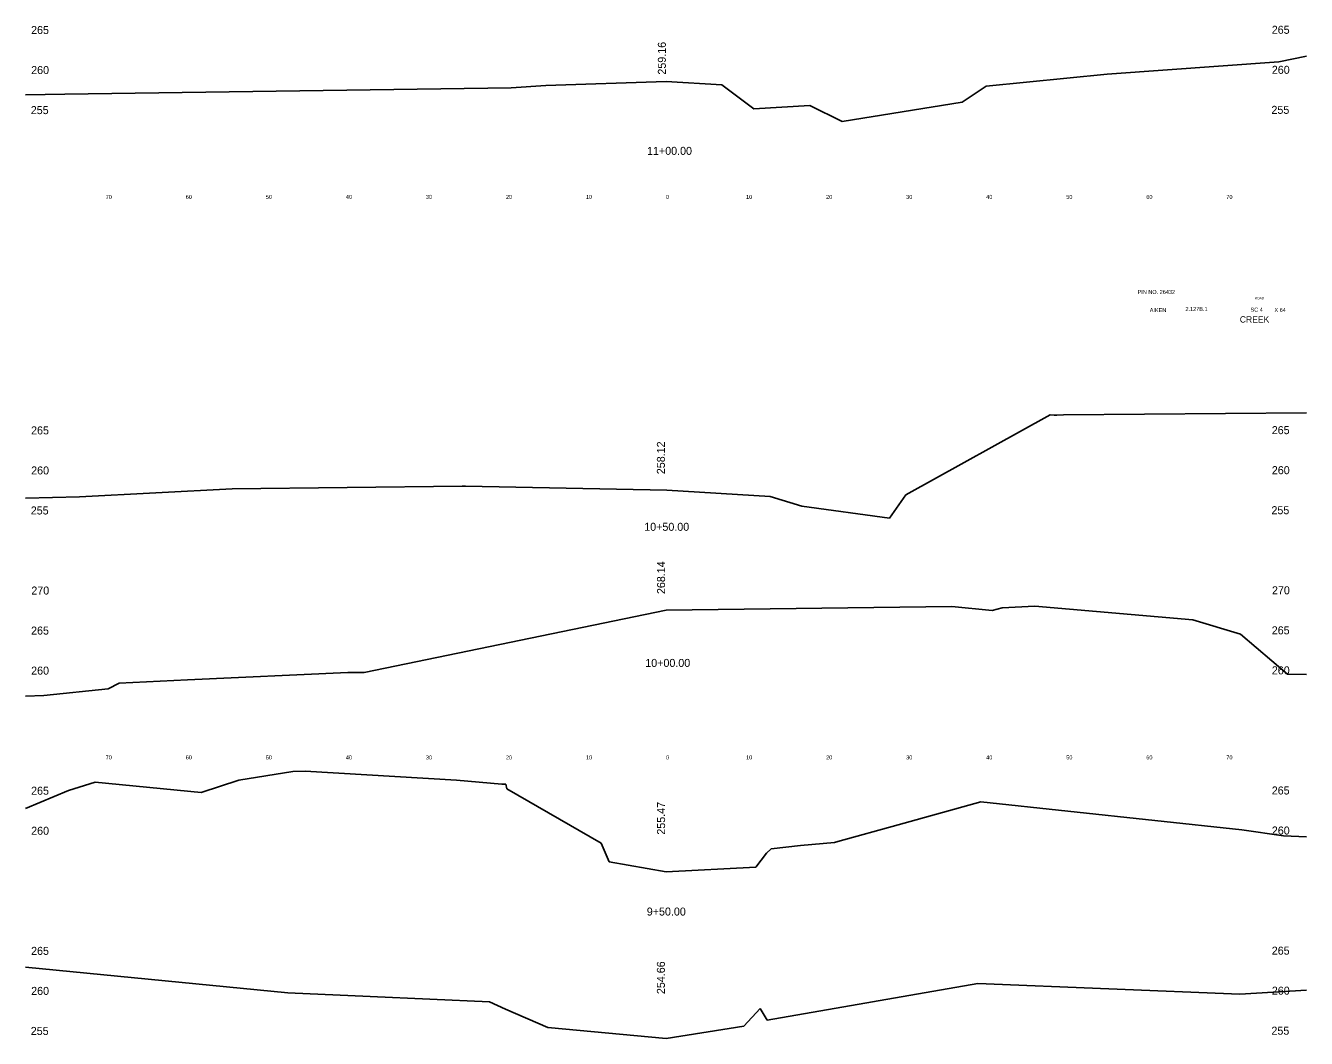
# Model space of a CAD drawing. Extents: x 175484 to 175644, y 176972 to 177478.
# Drawn here: x 175484.1 to 175644.1, y 177097.5 to 177223.9 of the extents above; entities that cross this region are included whole.
import ezdxf

# ---------------------------------------------------------------- set-up
doc = ezdxf.new("R2010")
doc.units = 0
for name, color, linetype in [('Level 1', 7, 'Continuous'), ('Level 10', 7, 'Continuous'), ('Level 2', 7, 'Continuous'), ('Level 3', 7, 'Continuous'), ('Level 60', 7, 'Continuous')]:
    doc.layers.add(name, color=color, linetype=linetype)

msp = doc.modelspace()

# ---------------------------------------------------------------- linework, layer by layer
at = {"layer": 'Level 60'}
for p, q in [((175619.24, 177217.88), (175640.67, 177219.42)), ((175640.67, 177219.42), (175644.13, 177220.11)), ((175604.13, 177216.37), (175619.24, 177217.88)), ((175489.03, 177215.36), (175544.8, 177216.16)), ((175544.8, 177216.16), (175549.13, 177216.46)), ((175549.13, 177216.46), (175564.13, 177216.96)), ((175564.13, 177216.96), (175571.12, 177216.56)), ((175571.12, 177216.56), (175575.11, 177213.56)), ((175601.12, 177214.36), (175604.13, 177216.37)), ((175484.13, 177215.28), (175486.58, 177215.34)), ((175486.58, 177215.34), (175489.03, 177215.36)), ((175575.11, 177213.56), (175582.11, 177213.96)), ((175582.11, 177213.96), (175586.13, 177211.96)), ((175586.13, 177211.96), (175601.12, 177214.36)), ((175594.1, 177165.36), (175612.12, 177175.32)), ((175612.12, 177175.32), (175612.61, 177175.29)), ((175612.61, 177175.29), (175612.96, 177175.31)), ((175612.96, 177175.31), (175613.77, 177175.33)), ((175613.77, 177175.33), (175644.13, 177175.57)), ((175509.95, 177166.08), (175538.67, 177166.42)), ((175538.67, 177166.42), (175539.1, 177166.43)), ((175539.1, 177166.43), (175564.25, 177165.92)), ((175484.13, 177164.91), (175490.86, 177165.09)), ((175490.86, 177165.09), (175509.95, 177166.08)), ((175564.25, 177165.92), (175577.14, 177165.13)), ((175577.14, 177165.13), (175581.11, 177163.94)), ((175592.06, 177162.43), (175594.1, 177165.36)), ((175581.11, 177163.94), (175592.06, 177162.43)), ((175526.41, 177143.16), (175564.13, 177150.94)), ((175564.13, 177150.94), (175599.82, 177151.4)), ((175599.82, 177151.4), (175604.86, 177150.88)), ((175604.86, 177150.88), (175606.12, 177151.23)), ((175606.12, 177151.23), (175610.2, 177151.42)), ((175610.2, 177151.42), (175629.96, 177149.72)), ((175629.96, 177149.72), (175635.9, 177147.95)), ((175635.9, 177147.95), (175641.78, 177142.94)), ((175504.36, 177142.22), (175524.38, 177143.16)), ((175524.38, 177143.16), (175525.71, 177143.16)), ((175525.71, 177143.16), (175526.41, 177143.16)), ((175641.78, 177142.94), (175644.13, 177142.9)), ((175486.39, 177140.27), (175494.42, 177141.11)), ((175494.42, 177141.11), (175495.8, 177141.82)), ((175495.8, 177141.82), (175504.36, 177142.22)), ((175484.13, 177140.19), (175486.39, 177140.27)), ((175506.06, 177128.16), (175510.78, 177129.72)), ((175510.78, 177129.72), (175517.51, 177130.79)), ((175517.51, 177130.79), (175519.05, 177130.82)), ((175519.05, 177130.82), (175537.94, 177129.71)), ((175537.94, 177129.71), (175543.62, 177129.21)), ((175484.13, 177126.18), (175489.5, 177128.41)), ((175489.5, 177128.41), (175492.82, 177129.45)), ((175492.82, 177129.45), (175506.06, 177128.16)), ((175543.62, 177129.21), (175544.1, 177129.21)), ((175544.1, 177129.21), (175544.24, 177128.62)), ((175544.24, 177128.62), (175556.03, 177121.84)), ((175593.13, 177124.14), (175603.45, 177127.02)), ((175603.45, 177127.02), (175636.05, 177123.51)), ((175585.61, 177122.04), (175593.13, 177124.14)), ((175636.05, 177123.51), (175641.27, 177122.75)), ((175556.03, 177121.84), (175557.04, 177119.52)), ((175580.94, 177121.53), (175585.19, 177121.91)), ((175585.19, 177121.91), (175585.61, 177122.04)), ((175641.27, 177122.75), (175644.13, 177122.64)), ((175575.34, 177118.86), (175576.67, 177120.6)), ((175576.67, 177120.6), (175577.25, 177121.13)), ((175577.25, 177121.13), (175580.94, 177121.53)), ((175557.04, 177119.52), (175564.13, 177118.27)), ((175564.13, 177118.27), (175575.34, 177118.86)), ((175484.13, 177106.37), (175516.89, 177103.17)), ((175576.78, 177099.75), (175603.07, 177104.3)), ((175603.07, 177104.3), (175635.83, 177102.98)), ((175516.89, 177103.17), (175527.16, 177102.7)), ((175527.16, 177102.7), (175542.08, 177102.02)), ((175635.83, 177102.98), (175644.13, 177103.5)), ((175542.08, 177102.02), (175544.08, 177101.13)), ((175544.08, 177101.13), (175549.36, 177098.84)), ((175573.85, 177098.99), (175575.9, 177101.18)), ((175575.9, 177101.18), (175576.78, 177099.75)), ((175549.36, 177098.84), (175564.13, 177097.46)), ((175564.13, 177097.46), (175573.85, 177098.99))]:
    msp.add_line(p, q, dxfattribs=at)

# ---------------------------------------------------------------- texts
at = {"layer": 'Level 1'}
for s, height, p in [('PIN NO. 26432', 0.5, (175623.04, 177190.43)), (' 2.127B.1', 0.5, (175628.83, 177188.3)), ('ROAD', 0.3, (175637.66, 177189.76)), ('AIKEN', 0.5, (175624.56, 177188.16)), ('CREEK', 0.8, (175635.81, 177186.85)), ('SC 4', 0.5, (175637.15, 177188.22)), ('X 64', 0.5, (175640.14, 177188.19))]:
    msp.add_text(s, height=height, dxfattribs=at).set_placement(p)
at = {"layer": 'Level 10'}
for s, p in [('259.16', (175564.11, 177217.82)), ('258.12', (175563.99, 177167.92)), ('268.14', (175564.01, 177152.95)), ('255.47', (175564.01, 177122.9)), ('254.66', (175563.99, 177102.99))]:
    msp.add_text(s, height=1, rotation=90, dxfattribs=at).set_placement(p)
for s, p in [('11+00.00', (175561.76, 177207.8)), ('10+50.00', (175561.41, 177160.85)), ('10+00.00', (175561.54, 177143.85)), ('9+50.00', (175561.73, 177112.8))]:
    msp.add_text(s, height=1, dxfattribs=at).set_placement(p)
at = {"layer": 'Level 2'}
for s, p in [('70', (175494.13, 177202.3)), ('60', (175504.13, 177202.3)), ('50', (175514.13, 177202.3)), ('40', (175524.13, 177202.3)), ('30', (175534.13, 177202.3)), ('20', (175544.13, 177202.3)), ('10', (175554.13, 177202.3)), ('0', (175564.13, 177202.3)), ('10', (175574.13, 177202.3)), ('20', (175584.13, 177202.3)), ('30', (175594.13, 177202.3)), ('40', (175604.13, 177202.3)), ('50', (175614.13, 177202.3)), ('60', (175624.13, 177202.3)), ('70', (175634.13, 177202.3)), ('70', (175494.13, 177132.3)), ('60', (175504.13, 177132.3)), ('50', (175514.13, 177132.3)), ('40', (175524.13, 177132.3)), ('30', (175534.13, 177132.3)), ('20', (175544.13, 177132.3)), ('10', (175554.13, 177132.3)), ('0', (175564.13, 177132.3)), ('10', (175574.13, 177132.3)), ('20', (175584.13, 177132.3)), ('30', (175594.13, 177132.3)), ('40', (175604.13, 177132.3)), ('50', (175614.13, 177132.3)), ('60', (175624.13, 177132.3)), ('70', (175634.13, 177132.3))]:
    msp.add_text(s, height=0.5, dxfattribs=at).set_placement(p)
at = {"layer": 'Level 3'}
for s, p in [(' 265', (175484.44, 177222.89)), (' 265', (175639.43, 177222.92)), (' 260', (175484.45, 177217.89)), (' 260', (175639.44, 177217.92)), (' 255', (175484.4, 177212.89)), (' 255', (175639.39, 177212.92)), (' 265', (175484.44, 177172.89)), (' 265', (175639.43, 177172.92)), (' 260', (175484.45, 177167.89)), (' 260', (175639.44, 177167.92)), (' 255', (175484.4, 177162.89)), (' 255', (175639.39, 177162.92)), (' 270', (175484.47, 177152.89)), (' 270', (175639.46, 177152.92)), (' 265', (175484.44, 177147.89)), (' 265', (175639.43, 177147.92)), (' 260', (175484.45, 177142.89)), (' 260', (175639.44, 177142.92)), (' 265', (175484.44, 177127.89)), (' 265', (175639.43, 177127.92)), (' 260', (175484.45, 177122.89)), (' 260', (175639.44, 177122.92)), (' 265', (175484.44, 177107.89)), (' 265', (175639.43, 177107.92)), (' 260', (175484.45, 177102.89)), (' 260', (175639.44, 177102.92)), (' 255', (175484.4, 177097.89)), (' 255', (175639.39, 177097.92))]:
    msp.add_text(s, height=1, dxfattribs=at).set_placement(p)

doc.saveas('drawing.dxf')
